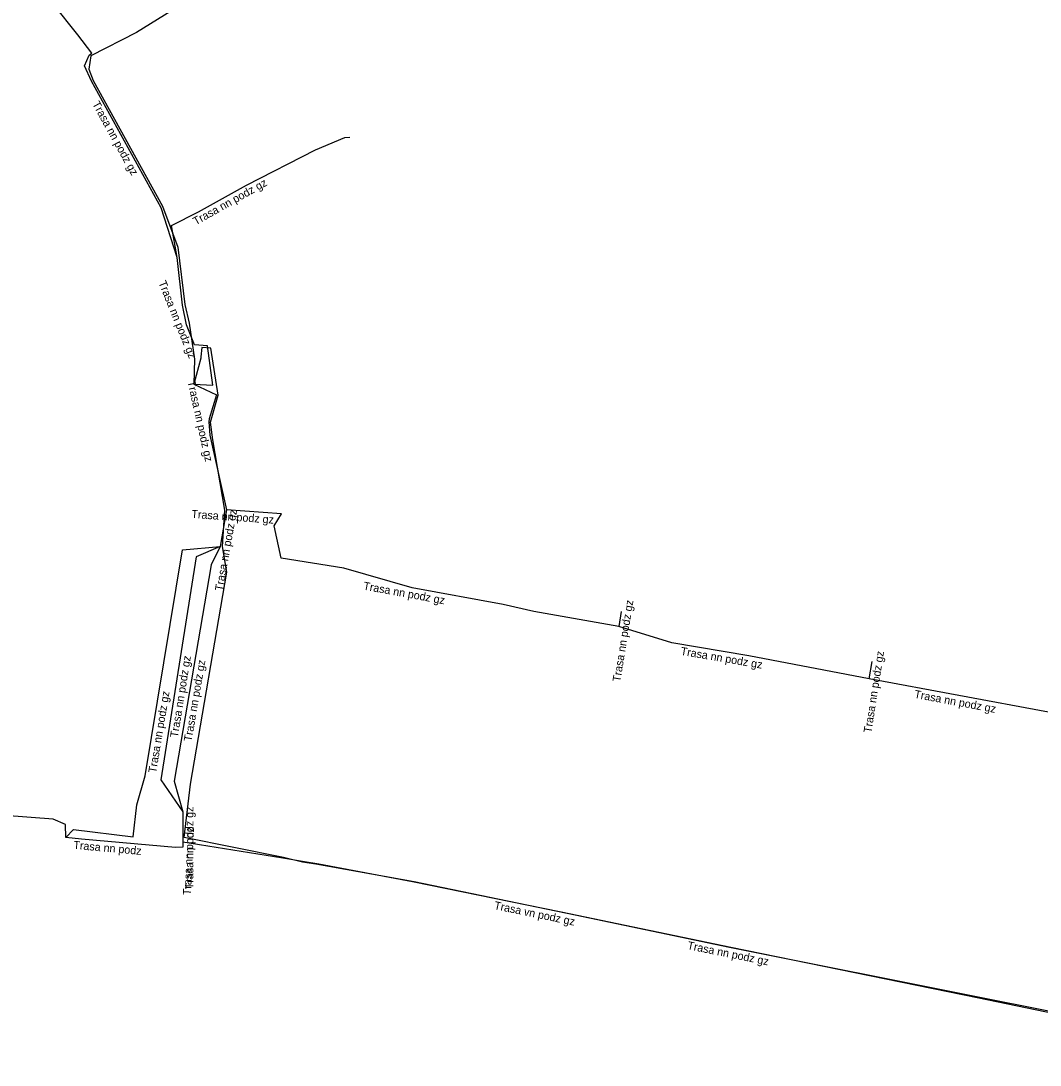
# Model space of a CAD drawing. Extents: x -687924 to -686708, y -1056742 to -1056249.
# Drawn here: x -687289.1 to -687225.4, y -1056479.5 to -1056414.3 of the extents above; entities that cross this region are included whole.
import ezdxf

# ---------------------------------------------------------------- set-up
doc = ezdxf.new("R2010")
doc.units = 0
for name, color, linetype in [('Popiskový text - Ostatní atributy Trasy', 7, 'Continuous'), ('Spojnice NN', 7, 'Continuous'), ('Spojnice VN', 7, 'Continuous')]:
    doc.layers.add(name, color=color, linetype=linetype)

msp = doc.modelspace()

# ---------------------------------------------------------------- linework, layer by layer
at = {"layer": 'Spojnice NN'}
for points in [[(-687284.61, -1056416.29), (-687285.5, -1056415.14), (-687287.06, -1056413.17), (-687287.89, -1056412.63), (-687289.09, -1056412.99), (-687291.59, -1056414.83), (-687294.9, -1056416.53), (-687298.62, -1056418.6), (-687300.06, -1056419.41), (-687302.29, -1056420.54), (-687303.16, -1056420.84)], [(-687279.3, -1056429.05), (-687280.3, -1056425.94), (-687284.64, -1056418.04), (-687285.07, -1056417.07), (-687284.79, -1056416.4), (-687284.61, -1056416.29)], [(-687279.3, -1056429.05), (-687279.64, -1056427.05), (-687277.95, -1056426.2), (-687274.97, -1056424.53), (-687270.66, -1056422.33), (-687268.82, -1056421.56), (-687268.5, -1056421.53)], [(-687278.24, -1056436.95), (-687277.06, -1056437.03), (-687277.39, -1056434.57), (-687278.2, -1056434.5), (-687278.7, -1056433.26), (-687278.96, -1056432.03), (-687279.3, -1056429.05)], [(-687278.24, -1056436.95), (-687276.84, -1056437.63), (-687277.29, -1056439.12), (-687277.31, -1056439.319), (-687277.24, -1056440.15), (-687276.201, -1056444.816)], [(-687276.201, -1056444.816), (-687276.61, -1056447.11)], [(-687272.77, -1056445.06), (-687276.201, -1056444.816)], [(-687251.71, -1056452.1), (-687257.02, -1056451.16), (-687258.93, -1056450.73), (-687264.62, -1056449.69), (-687268.89, -1056448.46), (-687272.8, -1056447.83), (-687273.24, -1056445.81), (-687272.77, -1056445.06)], [(-687286.25, -1056465.28), (-687285.76, -1056464.78), (-687282.03, -1056465.24), (-687281.8, -1056463.25), (-687281.29, -1056461.42), (-687278.95, -1056447.3), (-687276.61, -1056447.11)], [(-687276.61, -1056447.11), (-687278.1, -1056447.75), (-687280.32, -1056461.67), (-687278.93, -1056463.68)], [(-687276.61, -1056447.11), (-687277.16, -1056448.25), (-687279.47, -1056461.76), (-687278.93, -1056463.68)], [(-687251.56, -1056451.17), (-687251.71, -1056452.1)], [(-687236.06, -1056455.37), (-687243.58, -1056453.94), (-687248.39, -1056453.12), (-687251.71, -1056452.1)], [(-687236.06, -1056455.37), (-687235.89, -1056454.28)], [(-687222.58, -1056457.71), (-687224.87, -1056457.46), (-687236.06, -1056455.37)], [(-687286.25, -1056465.28), (-687286.27, -1056464.47), (-687287.04, -1056464.14), (-687290.05, -1056463.91), (-687291.26, -1056463.85), (-687292.13, -1056463.81), (-687292.82, -1056463.8), (-687304.95, -1056462.91), (-687306.1, -1056462.89)], [(-687278.93, -1056463.68), (-687278.93, -1056465.56)], [(-687278.945, -1056465.881), (-687279.395, -1056465.911), (-687285.259, -1056465.38), (-687286.25, -1056465.28)], [(-687278.93, -1056465.56), (-687278.945, -1056465.881)], [(-687278.93, -1056465.56), (-687272.69, -1056466.55), (-687271.46, -1056466.75), (-687270.44, -1056466.93), (-687264.59, -1056468.03), (-687255.31, -1056469.93), (-687244.72, -1056472.14), (-687229.23, -1056475.29), (-687218.57, -1056477.5), (-687213.58, -1056478.45), (-687213.33, -1056478.46), (-687212.11, -1056478.65), (-687209.26, -1056479.35), (-687208.15, -1056479.5)]]:
    msp.add_lwpolyline(points, dxfattribs=at)
at = {"layer": 'Spojnice VN'}
for points in [[(-687278.78, -1056413.1), (-687281.83, -1056414.99), (-687284.68, -1056416.45), (-687284.81, -1056417.28), (-687284.54, -1056417.99), (-687280.2, -1056425.85), (-687279.24, -1056428.4), (-687278.82, -1056431.99), (-687278.54, -1056433.14), (-687278.207, -1056435.394), (-687278.24, -1056436.95)], [(-687221.2, -1056476.85), (-687229.16, -1056475.28), (-687244.79, -1056472.16), (-687254.44, -1056470.14), (-687264.49, -1056468.05), (-687270.62, -1056466.95), (-687271.47, -1056466.82), (-687272.64, -1056466.52), (-687278.85, -1056465.29), (-687278.46, -1056461.94), (-687276.19, -1056448.7), (-687276.46, -1056447.1), (-687276.309, -1056444.834), (-687277.06, -1056440.44), (-687277.2, -1056439.34), (-687277.17, -1056439.18), (-687276.73, -1056437.64), (-687277.19, -1056434.72), (-687277.75, -1056434.67), (-687277.821, -1056435.262), (-687277.811, -1056435.336), (-687278.24, -1056436.95)]]:
    msp.add_lwpolyline(points, dxfattribs=at)

# ---------------------------------------------------------------- texts
at = {"layer": 'Popiskový text - Ostatní atributy Trasy'}
for s, rotation, p in [('Trasa nn podz gz', 298.78295, (-687284.609, -1056419.447)), ('Trasa nn podz gz', 29.26639, (-687278.128, -1056427.045)), ('Trasa nn podz gz', 291.96056, (-687280.468, -1056430.614)), ('Trasa nn podz gz', 282.55351, (-687278.652, -1056436.8)), ('Trasa nn podz gz', 355.93219, (-687278.416, -1056445.31)), ('Trasa nn podz gz', 79.89089, (-687276.449, -1056449.91)), ('Trasa nn podz gz', 349.642, (-687267.692, -1056449.789)), ('Trasa nn podz gz', 80.83765, (-687251.613, -1056455.583)), ('Trasa nn podz gz', 350.32533, (-687247.871, -1056453.868)), ('Trasa nn podz gz', 81.13538, (-687235.933, -1056458.773)), ('Trasa nn podz gz', 80.93862, (-687279.246, -1056459.063)), ('Trasa nn podz gz', 80.29714, (-687278.392, -1056459.312)), ('Trasa nn podz gz', 80.59033, (-687280.607, -1056461.274)), ('Trasa nn podz gz', 349.42054, (-687233.279, -1056456.551)), ('Trasa nn podz gz', 90, (-687278.28, -1056468.514)), ('Trasa nn podz', 87.32457, (-687278.435, -1056468.895)), ('Trasa nn podz', 354.82765, (-687285.791, -1056465.985)), ('Trasa vn podz gz', 348.2522, (-687259.521, -1056469.747)), ('Trasa nn podz gz', 348.50524, (-687247.455, -1056472.247))]:
    msp.add_text(s, height=0.5, rotation=rotation, dxfattribs=at).set_placement(p)

doc.saveas('drawing.dxf')
